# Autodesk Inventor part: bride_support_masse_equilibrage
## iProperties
Created: 2011-01
Part Number: bride_support_masse_equilibrage
Document SubType Name: Modeling
Designer: eric
Density: 1 g/cm^3
Mass: 7.50876 g
Surface Area: 126.265 cm^2
Volume: 7.50876 cm^3
Author: eric
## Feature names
1. Base1
